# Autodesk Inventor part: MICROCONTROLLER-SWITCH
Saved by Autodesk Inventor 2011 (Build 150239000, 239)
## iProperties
Created: 2007-09
Part Number: MICROCONTROLLER-SWITCH
Document SubType Name: Modeling
Density: 1 g/cm^3
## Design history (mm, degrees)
feature "Base1"
body "Solid1"
